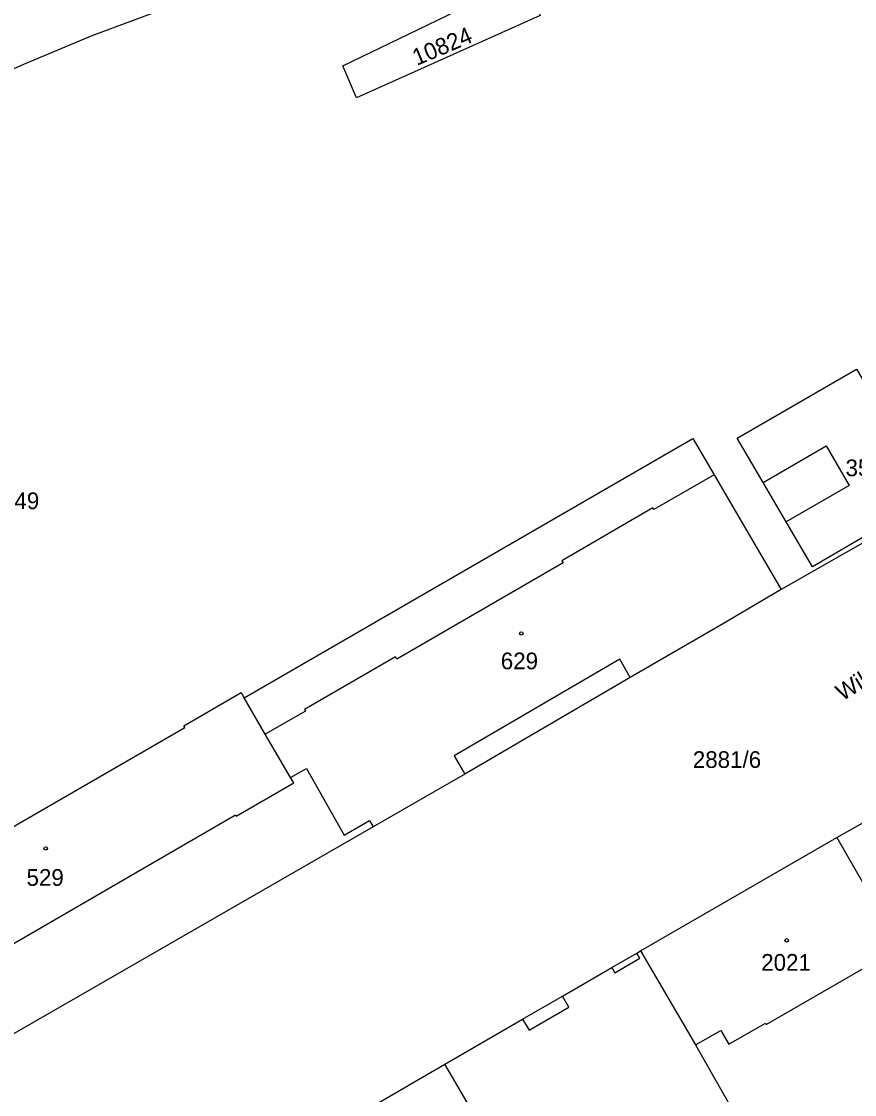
# Model space of a CAD drawing. Extents: x -564952 to -564307, y -1202373 to -1201847.
# Drawn here: x -564730.1 to -564645.4, y -1202200.5 to -1202091.3 of the extents above; entities that cross this region are included whole.
import ezdxf

# ---------------------------------------------------------------- set-up
doc = ezdxf.new("R2010")
doc.units = 0
for name, color, linetype in [('Hranice parcel', 7, 'Continuous'), ('Parcelní čísla', 7, 'Continuous'), ('Pop  PČ popisy', 7, 'Continuous'), ('Vnitřní kresba', 7, 'Continuous'), ('Značky budov', 7, 'Continuous')]:
    doc.layers.add(name, color=color, linetype=linetype)

msp = doc.modelspace()

# ---------------------------------------------------------------- linework, layer by layer
at = {"layer": 'Hranice parcel'}
for p, q in [((-564707.49, -1202160.1), (-564661.83, -1202133.72)), ((-564634.78, -1202138.78), (-564652.84, -1202149.09)), ((-564656.9, -1202142.15), (-564652.84, -1202149.09)), ((-564652.84, -1202149.09), (-564658.86, -1202152.65)), ((-564707.79, -1202159.58), (-564707.49, -1202160.1)), ((-564647.18, -1202174.34), (-564629.78, -1202164.5)), ((-564667.14, -1202185.87), (-564647.18, -1202174.34)), ((-564667.14, -1202185.87), (-564661.56, -1202195.43)), ((-564694.52, -1202201.73), (-564687.07, -1202197.41))]:
    msp.add_line(p, q, dxfattribs=at)
for points in [[(-564637.69, -1202058.81), (-564638.03, -1202059.06), (-564655, -1202066.79), (-564662.43, -1202069.69), (-564704.06, -1202085.69), (-564722.99, -1202092.74), (-564729.95, -1202095.67), (-564736.84, -1202098.72), (-564741.32, -1202100.95), (-564768.52, -1202116.71), (-564777.25, -1202121.88), (-564783.74, -1202125.64), (-564785.97, -1202126.79), (-564816.39, -1202144.49)], [(-564697.44, -1202095.78), (-564679.17, -1202086.93), (-564677.37, -1202090.67), (-564696.04, -1202099.05), (-564697.44, -1202095.78)], [(-564649.66, -1202146.78), (-564652.32, -1202142.22), (-564654.66, -1202138.21), (-564657.3, -1202133.69), (-564645.16, -1202126.66), (-564637.48, -1202139.67), (-564649.66, -1202146.78)], [(-564661.83, -1202133.72), (-564659.67, -1202137.41), (-564656.9, -1202142.15)], [(-564658.86, -1202152.65), (-564668.19, -1202158.04), (-564685.03, -1202167.87), (-564694.35, -1202173.24)], [(-564746.42, -1202194.29), (-564751.8, -1202185.07), (-564746.02, -1202181.72), (-564745.95, -1202181.85), (-564713.53, -1202163.13), (-564713.63, -1202162.96), (-564707.79, -1202159.58)], [(-564702.76, -1202168.23), (-564705.33, -1202163.82), (-564707.49, -1202160.1)], [(-564702.76, -1202168.23), (-564701.13, -1202167.31), (-564697.31, -1202174.08)], [(-564746.42, -1202194.29), (-564740.54, -1202190.88), (-564740.63, -1202190.71), (-564708.37, -1202172.01), (-564708.29, -1202172.15), (-564702.44, -1202168.76), (-564702.76, -1202168.23)], [(-564694.35, -1202173.24), (-564735.89, -1202197.13), (-564730.32, -1202210.59), (-564747.11, -1202220.56)], [(-564697.31, -1202174.08), (-564694.74, -1202172.59), (-564694.35, -1202173.24)], [(-564647.18, -1202174.34), (-564641.67, -1202183.91), (-564640.9, -1202185.58), (-564639.75, -1202188.35)], [(-564687.07, -1202197.41), (-564679.15, -1202192.82), (-564675.09, -1202190.47), (-564670.07, -1202187.57), (-564667.53, -1202186.1), (-564667.14, -1202185.87)], [(-564661.56, -1202195.43), (-564657.9, -1202201.87), (-564654.13, -1202208.52)], [(-564675.55, -1202217.24), (-564682.1, -1202205.88), (-564687.07, -1202197.41)]]:
    msp.add_lwpolyline(points, dxfattribs=at)
at = {"layer": 'Vnitřní kresba'}
for p, q in [((-564654.66, -1202138.21), (-564648.27, -1202134.48)), ((-564648.27, -1202134.48), (-564645.93, -1202138.49)), ((-564659.67, -1202137.41), (-564665.8, -1202140.95)), ((-564645.93, -1202138.49), (-564652.32, -1202142.22)), ((-564665.9, -1202140.78), (-564675.16, -1202146.16)), ((-564665.8, -1202140.95), (-564665.9, -1202140.78)), ((-564675.02, -1202146.39), (-564691.95, -1202156.19)), ((-564675.16, -1202146.16), (-564675.02, -1202146.39)), ((-564692.09, -1202155.95), (-564701.33, -1202161.3)), ((-564691.95, -1202156.19), (-564692.09, -1202155.95)), ((-564669.27, -1202156.19), (-564686.12, -1202166.01)), ((-564668.19, -1202158.04), (-564669.27, -1202156.19)), ((-564701.33, -1202161.3), (-564701.24, -1202161.46)), ((-564701.24, -1202161.46), (-564705.33, -1202163.82)), ((-564686.12, -1202166.01), (-564685.03, -1202167.87)), ((-564667.23, -1202186.62), (-564667.53, -1202186.1)), ((-564654.37, -1202193.36), (-564640.9, -1202185.58)), ((-564669.77, -1202188.09), (-564667.23, -1202186.62)), ((-564670.07, -1202187.57), (-564669.77, -1202188.09)), ((-564674.44, -1202191.6), (-564675.09, -1202190.47)), ((-564678.49, -1202193.95), (-564674.44, -1202191.6)), ((-564679.15, -1202192.82), (-564678.49, -1202193.95)), ((-564661.56, -1202195.43), (-564658.98, -1202193.99)), ((-564658.98, -1202193.99), (-564658.17, -1202195.36)), ((-564658.17, -1202195.36), (-564654.44, -1202193.24)), ((-564654.44, -1202193.24), (-564654.37, -1202193.36))]:
    msp.add_line(p, q, dxfattribs=at)
at = {"layer": 'Značky budov'}
for centre in [(-564679.28, -1202153.56), (-564727.68, -1202175.44), (-564652.28, -1202184.8)]:
    msp.add_circle(centre, 0.175, dxfattribs=at)

# ---------------------------------------------------------------- texts
at = {"layer": 'Parcelní čísla'}
msp.add_text('10824', height=1.7, rotation=23, dxfattribs=at).set_placement((-564689.92, -1202095.81))
for s, p in [('3560', (-564646.29, -1202137.56)), ('2864/649', (-564737.82, -1202140.91)), ('629', (-564681.37, -1202157.21)), ('2881/6', (-564661.83, -1202167.25)), ('529', (-564729.63, -1202179.25)), ('2021', (-564654.87, -1202187.89))]:
    msp.add_text(s, height=1.7, dxfattribs=at).set_placement(p)
at = {"layer": 'Pop  PČ popisy'}
msp.add_text('Wilsonova', height=1.7, rotation=31, dxfattribs=at).set_placement((-564646.62, -1202160.48))

doc.saveas('drawing.dxf')
